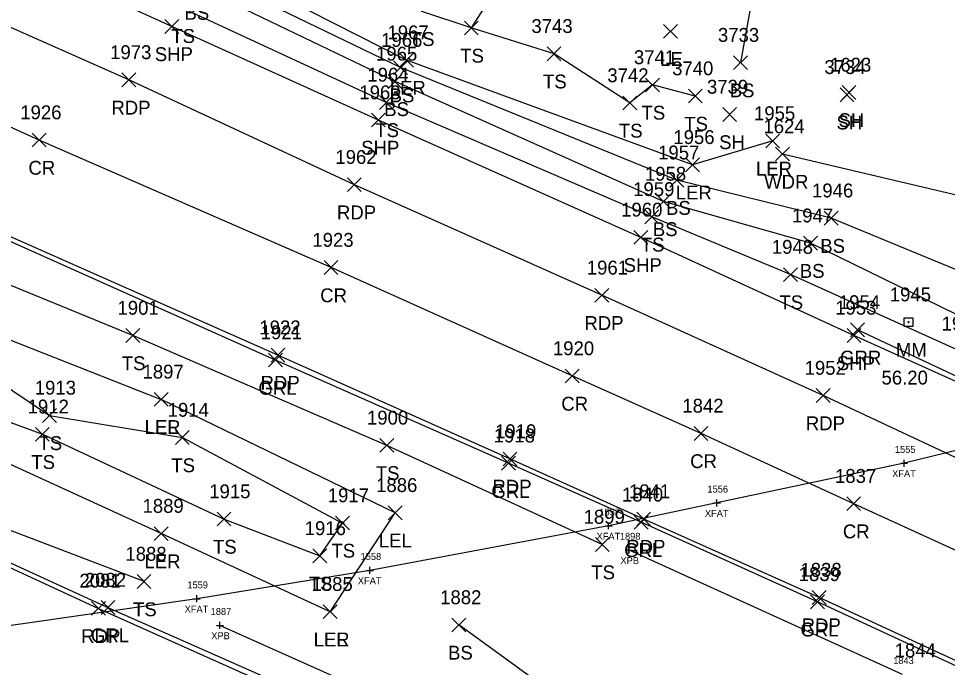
# Model space of a CAD drawing. Extents: x 1599569 to 1610055, y 642560 to 647860.
# Drawn here: x 1601517.7 to 1601651.7, y 647279.1 to 647372.7 of the extents above; entities that cross this region are included whole.
import ezdxf

# ---------------------------------------------------------------- set-up
doc = ezdxf.new("R2010")
doc.units = 0
for name, color, linetype in [('B_A', 7, 'Continuous'), ('B_I', 7, 'Continuous'), ('B_TIC', 7, 'Continuous'), ('BF', 7, 'Continuous'), ('BSUBM', 7, 'Continuous'), ('L_A', 7, 'Continuous'), ('L_I', 7, 'Continuous'), ('L_TIC', 7, 'Continuous'), ('LARO', 7, 'Continuous'), ('LAWA', 7, 'Continuous'), ('LELB', 7, 'Continuous'), ('P_A', 7, 'Continuous'), ('P_I', 7, 'Continuous'), ('P_TIC', 7, 'Continuous'), ('PET', 7, 'Continuous'), ('PRC', 7, 'Continuous'), ('PSP', 7, 'Continuous'), ('R_A', 7, 'Continuous'), ('R_I', 7, 'Continuous'), ('R_TIC', 7, 'Continuous'), ('RGR', 7, 'Continuous'), ('S_A', 7, 'Continuous'), ('S_C', 7, 'Continuous'), ('S_I', 7, 'Continuous'), ('SRM', 7, 'Continuous')]:
    doc.layers.add(name, color=color, linetype=linetype)

msp = doc.modelspace()

# ---------------------------------------------------------------- linework, layer by layer
at = {"layer": 'B_TIC'}
for p, q in [((1601645.46, 647308.52), (1601645.53, 647308.52)), ((1601618.44, 647302.79), (1601618.51, 647302.79)), ((1601602.81, 647299.49), (1601602.88, 647299.49)), ((1601605.77, 647295.98), (1601605.84, 647295.98)), ((1601568.36, 647293.07), (1601568.43, 647293.07)), ((1601543.36, 647288.97), (1601543.44, 647288.97)), ((1601546.72, 647285.13), (1601546.8, 647285.13))]:
    msp.add_line(p, q, dxfattribs=at)
for points in [[(1601645.45, 647308.02), (1601645.45, 647309.02)], [(1601644.95, 647308.52), (1601645.95, 647308.52)], [(1601618.43, 647302.29), (1601618.43, 647303.29)], [(1601617.93, 647302.79), (1601618.93, 647302.79)], [(1601602.3, 647299.49), (1601603.3, 647299.49)], [(1601602.8, 647298.99), (1601602.8, 647299.99)], [(1601605.26, 647295.98), (1601606.26, 647295.98)], [(1601605.76, 647295.48), (1601605.76, 647296.48)], [(1601567.85, 647293.07), (1601568.85, 647293.07)], [(1601568.35, 647292.57), (1601568.35, 647293.57)], [(1601542.86, 647288.97), (1601543.86, 647288.97)], [(1601543.36, 647288.47), (1601543.36, 647289.47)], [(1601546.22, 647285.13), (1601547.22, 647285.13)], [(1601546.72, 647284.63), (1601546.72, 647285.63)]]:
    msp.add_lwpolyline(points, dxfattribs=at)
at = {"layer": 'BF'}
msp.add_lwpolyline([(1601746.01, 647335.35), (1601717.79, 647327.14), (1601692.8, 647320.35), (1601677.17, 647316.27), (1601645.45, 647308.52), (1601618.43, 647302.79), (1601602.8, 647299.49), (1601568.35, 647293.07), (1601543.36, 647288.97), (1601510.51, 647284.26), (1601475.95, 647280.39), (1601455.15, 647278.22), (1601422.22, 647275.79), (1601394.01, 647274.26), (1601380.77, 647273.7), (1601345.12, 647272.82), (1601321.94, 647272.73), (1601290.34, 647273.17)], dxfattribs=at)
at = {"layer": 'BSUBM'}
for points in [[(1601645.21, 647278.05), (1601605.76, 647295.98)], [(1601588.89, 647266.27), (1601546.72, 647285.13)]]:
    msp.add_lwpolyline(points, dxfattribs=at)
at = {"layer": 'L_TIC'}
for points in [[(1601581.98, 647370.32), (1601583.98, 647372.32)], [(1601583.98, 647370.32), (1601581.98, 647372.32)], [(1601581.98, 647370.32), (1601583.98, 647372.32)], [(1601583.98, 647370.32), (1601581.98, 647372.32)], [(1601610.73, 647369.84), (1601612.73, 647371.84)], [(1601612.73, 647369.84), (1601610.73, 647371.84)], [(1601572.63, 647365.69), (1601574.63, 647367.69)], [(1601574.63, 647365.69), (1601572.63, 647367.69)], [(1601593.92, 647366.6), (1601595.92, 647368.6)], [(1601595.92, 647366.6), (1601593.92, 647368.6)], [(1601571.76, 647364.6), (1601573.76, 647366.6)], [(1601573.76, 647364.6), (1601571.76, 647366.6)], [(1601620.83, 647365.32), (1601622.83, 647367.32)], [(1601622.83, 647365.32), (1601620.83, 647367.32)], [(1601570.98, 647362.61), (1601572.98, 647364.61)], [(1601572.98, 647362.61), (1601570.98, 647364.61)], [(1601608.14, 647362.1), (1601610.14, 647364.1)], [(1601610.14, 647362.1), (1601608.14, 647364.1)], [(1601614.31, 647360.5), (1601616.31, 647362.5)], [(1601616.31, 647360.5), (1601614.31, 647362.5)], [(1601636.2, 647360.68), (1601638.2, 647362.68)], [(1601638.2, 647360.68), (1601636.2, 647362.68)], [(1601636.49, 647361.02), (1601638.49, 647363.02)], [(1601638.49, 647361.02), (1601636.49, 647363.02)], [(1601569.72, 647359.58), (1601571.72, 647361.58)], [(1601571.72, 647359.58), (1601569.72, 647361.58)], [(1601604.87, 647359.5), (1601606.87, 647361.5)], [(1601606.87, 647359.5), (1601604.87, 647361.5)], [(1601619.26, 647357.84), (1601621.26, 647359.84)], [(1601621.26, 647357.84), (1601619.26, 647359.84)], [(1601625.48, 647354.02), (1601627.48, 647356.02)], [(1601627.48, 647354.02), (1601625.48, 647356.02)], [(1601626.88, 647352.13), (1601628.88, 647354.13)], [(1601628.88, 647352.13), (1601626.88, 647354.13)], [(1601613.89, 647350.58), (1601615.89, 647352.58)], [(1601615.89, 647350.58), (1601613.89, 647352.58)], [(1601611.64, 647348.36), (1601613.64, 647350.36)], [(1601613.64, 647348.36), (1601611.64, 647350.36)], [(1601609.73, 647345.29), (1601611.73, 647347.29)], [(1601611.73, 647345.29), (1601609.73, 647347.29)], [(1601608.04, 647343.07), (1601610.04, 647345.07)], [(1601610.04, 647343.07), (1601608.04, 647345.07)], [(1601633.9, 647342.88), (1601635.9, 647344.88)], [(1601635.9, 647342.88), (1601633.9, 647344.88)], [(1601630.94, 647339.27), (1601632.94, 647341.27)], [(1601632.94, 647339.27), (1601630.94, 647341.27)], [(1601628.05, 647334.74), (1601630.05, 647336.74)], [(1601630.05, 647334.74), (1601628.05, 647336.74)], [(1601533.14, 647325.95), (1601535.14, 647327.95)], [(1601535.14, 647325.95), (1601533.14, 647327.95)], [(1601537.23, 647316.74), (1601539.23, 647318.74)], [(1601539.23, 647316.74), (1601537.23, 647318.74)], [(1601537.23, 647316.74), (1601539.23, 647318.74)], [(1601539.23, 647316.74), (1601537.23, 647318.74)], [(1601521.12, 647314.42), (1601523.12, 647316.42)], [(1601523.12, 647314.42), (1601521.12, 647316.42)], [(1601520.09, 647311.7), (1601522.09, 647313.7)], [(1601522.09, 647311.7), (1601520.09, 647313.7)], [(1601540.29, 647311.23), (1601542.29, 647313.23)], [(1601542.29, 647311.23), (1601540.29, 647313.23)], [(1601569.79, 647310.1), (1601571.79, 647312.1)], [(1601571.79, 647310.1), (1601569.79, 647312.1)], [(1601571, 647300.37), (1601573, 647302.37)], [(1601573, 647300.37), (1601571, 647302.37)], [(1601546.3, 647299.47), (1601548.3, 647301.47)], [(1601548.3, 647299.47), (1601546.3, 647301.47)], [(1601563.39, 647298.9), (1601565.39, 647300.9)], [(1601565.39, 647298.9), (1601563.39, 647300.9)], [(1601563.39, 647298.9), (1601565.39, 647300.9)], [(1601565.39, 647298.9), (1601563.39, 647300.9)], [(1601537.24, 647297.37), (1601539.24, 647299.37)], [(1601539.24, 647297.37), (1601537.24, 647299.37)], [(1601600.89, 647295.79), (1601602.89, 647297.79)], [(1601602.89, 647295.79), (1601600.89, 647297.79)], [(1601560.12, 647294.15), (1601562.12, 647296.15)], [(1601562.12, 647294.15), (1601560.12, 647296.15)], [(1601534.76, 647290.45), (1601536.76, 647292.45)], [(1601536.76, 647290.45), (1601534.76, 647292.45)], [(1601561.62, 647286.1), (1601563.62, 647288.1)], [(1601563.62, 647286.1), (1601561.62, 647288.1)], [(1601561.62, 647286.1), (1601563.62, 647288.1)], [(1601563.62, 647286.1), (1601561.62, 647288.1)], [(1601580.18, 647284.19), (1601582.18, 647286.19)], [(1601582.18, 647284.19), (1601580.18, 647286.19)]]:
    msp.add_lwpolyline(points, dxfattribs=at)
at = {"layer": 'LARO'}
for points in [[(1601626.48, 647355.02), (1601614.89, 647351.58), (1601573.63, 647366.69), (1601545.56, 647380.95), (1601537.28, 647395.48)], [(1601562.62, 647287.1), (1601538.24, 647298.37), (1601510.12, 647311.25), (1601479.02, 647323.89), (1601477.41, 647331.44), (1601485.68, 647335.15), (1601504.04, 647331.18), (1601538.23, 647317.74)], [(1601562.62, 647287.1), (1601572, 647301.37), (1601538.23, 647317.74)]]:
    msp.add_lwpolyline(points, dxfattribs=at)
at = {"layer": 'LAWA'}
msp.add_lwpolyline([(1601848.49, 647386.96), (1601821.55, 647376.37), (1601804, 647372.6), (1601777.94, 647362.34), (1601760.01, 647349.17), (1601740.19, 647347.52), (1601705.98, 647345.02), (1601664.4, 647344.49), (1601627.88, 647353.13)], dxfattribs=at)
at = {"layer": 'LELB'}
for points in [[(1601623.48, 647409.22), (1601596.3, 647389.79), (1601588.83, 647380.5), (1601582.98, 647371.32), (1601575.85, 647373.72), (1601573.22, 647381.22), (1601572.13, 647391.97), (1601563.55, 647393.07), (1601555.46, 647392.28), (1601552.13, 647388), (1601566.58, 647377.81)], [(1601623.48, 647409.22), (1601626.37, 647391.44), (1601621.83, 647366.32)], [(1601850.43, 647302.21), (1601817.07, 647284.74), (1601803.58, 647280.33), (1601784.13, 647281.69), (1601758.75, 647290.86), (1601723.07, 647307), (1601685.47, 647323.96), (1601675.62, 647324.78), (1601658.01, 647334.35), (1601634.9, 647343.88), (1601612.64, 647349.36), (1601572.76, 647365.6), (1601544.62, 647379.24), (1601520.15, 647401.41)], [(1601803.11, 647261.21), (1601778.68, 647271.51), (1601755.32, 647284.83), (1601720.1, 647301.53), (1601682.66, 647319.41), (1601674.11, 647321.15), (1601654.95, 647329.02), (1601631.94, 647340.27), (1601610.73, 647346.29), (1601571.98, 647363.61), (1601543.15, 647377.5), (1601514.76, 647392.23)], [(1601677.57, 647312.89), (1601653.54, 647324.67), (1601629.05, 647335.74), (1601609.04, 647344.07), (1601570.72, 647360.58), (1601541.29, 647374.16), (1601512.39, 647387.81)], [(1601615.31, 647361.5), (1601609.14, 647363.1), (1601605.87, 647360.5), (1601594.92, 647367.6), (1601582.98, 647371.32)], [(1601601.89, 647296.79), (1601570.79, 647311.1), (1601534.14, 647326.95), (1601503.04, 647339.71), (1601477.7, 647352.04), (1601450.37, 647365.08)], [(1601535.76, 647291.45), (1601504.48, 647303.39), (1601475.12, 647316.86), (1601435.65, 647334.74), (1601403.81, 647348.42)], [(1601485.77, 647329.42), (1601503.55, 647327.86), (1601522.12, 647315.42), (1601541.29, 647312.23), (1601564.39, 647299.9)], [(1601485.77, 647329.42), (1601503.31, 647319.28), (1601521.09, 647312.7), (1601547.3, 647300.47), (1601561.12, 647295.15), (1601564.39, 647299.9)], [(1601962.97, 647113.31), (1601923.69, 647130.08), (1601895.55, 647143.8), (1601852.73, 647162.89), (1601817.77, 647178.58), (1601769.5, 647198.02), (1601730.98, 647216.5), (1601688.1, 647233.1), (1601653.57, 647246.64), (1601608.27, 647265.53), (1601581.18, 647285.19)]]:
    msp.add_lwpolyline(points, dxfattribs=at)
at = {"layer": 'P_TIC'}
for points in [[(1601538.77, 647370.54), (1601540.77, 647372.54)], [(1601540.77, 647370.54), (1601538.77, 647372.54)], [(1601532.57, 647362.83), (1601534.57, 647364.83)], [(1601534.57, 647362.83), (1601532.57, 647364.83)], [(1601568.57, 647357.04), (1601570.57, 647359.04)], [(1601570.57, 647357.04), (1601568.57, 647359.04)], [(1601519.64, 647354.15), (1601521.64, 647356.15)], [(1601521.64, 647354.15), (1601519.64, 647356.15)], [(1601565.11, 647347.71), (1601567.11, 647349.71)], [(1601567.11, 647347.71), (1601565.11, 647349.71)], [(1601606.44, 647340.11), (1601608.44, 647342.11)], [(1601608.44, 647340.11), (1601606.44, 647342.11)], [(1601561.74, 647335.75), (1601563.74, 647337.75)], [(1601563.74, 647335.75), (1601561.74, 647337.75)], [(1601600.82, 647331.75), (1601602.82, 647333.75)], [(1601602.82, 647331.75), (1601600.82, 647333.75)], [(1601637.2, 647325.96), (1601639.2, 647327.96)], [(1601639.2, 647325.96), (1601637.2, 647327.96)], [(1601554.09, 647323.12), (1601556.09, 647325.12)], [(1601556.09, 647323.12), (1601554.09, 647325.12)], [(1601596.54, 647320.11), (1601598.54, 647322.11)], [(1601598.54, 647320.11), (1601596.54, 647322.11)], [(1601632.77, 647317.29), (1601634.77, 647319.29)], [(1601634.77, 647317.29), (1601632.77, 647319.29)], [(1601615.13, 647311.82), (1601617.13, 647313.82)], [(1601617.13, 647311.82), (1601615.13, 647313.82)], [(1601587.56, 647308.14), (1601589.56, 647310.14)], [(1601589.56, 647308.14), (1601587.56, 647310.14)], [(1601637.16, 647301.69), (1601639.16, 647303.69)], [(1601639.16, 647301.69), (1601637.16, 647303.69)], [(1601606.86, 647299.47), (1601608.86, 647301.47)], [(1601608.86, 647299.47), (1601606.86, 647301.47)], [(1601632.17, 647288.14), (1601634.17, 647290.14)], [(1601634.17, 647288.14), (1601632.17, 647290.14)], [(1601528.2, 647286.58), (1601530.2, 647288.58)], [(1601530.2, 647286.58), (1601528.2, 647288.58)]]:
    msp.add_lwpolyline(points, dxfattribs=at)
at = {"layer": 'PET'}
for points in [[(1602047.79, 647130.94), (1602008.9, 647148.2), (1601944.5, 647177.36), (1601896.5, 647199.08), (1601839.98, 647224.8), (1601799.6, 647242.94), (1601761.01, 647260.23), (1601722.86, 647277.56), (1601690.61, 647292.09), (1601662.07, 647305.04), (1601633.77, 647318.29), (1601601.82, 647332.75), (1601566.11, 647348.71), (1601533.57, 647363.83), (1601469.6, 647392.2)], [(1601973.38, 647134.15), (1601930.79, 647153.54), (1601888.64, 647172.44), (1601843.17, 647192.94), (1601801.06, 647212.25), (1601760.52, 647230.65), (1601718.64, 647249.66), (1601675.39, 647269.62), (1601633.17, 647289.14), (1601607.86, 647300.47), (1601588.56, 647309.14), (1601555.09, 647324.12), (1601512, 647343.16), (1601472.14, 647361.1), (1601457.8, 647367.35)], [(1601401.84, 647345.99), (1601436.76, 647329.85), (1601477.89, 647310.69), (1601511.69, 647295.64), (1601529.2, 647287.58), (1601568.21, 647270.13), (1601613.57, 647249.46), (1601666.31, 647226.36), (1601709.07, 647207.41), (1601751.08, 647188.42), (1601796.47, 647168.32), (1601839.63, 647148.76), (1601881.89, 647129.58), (1601912.89, 647115.63)]]:
    msp.add_lwpolyline(points, dxfattribs=at)
at = {"layer": 'PRC'}
msp.add_lwpolyline([(1602004.91, 647136.4), (1601979.09, 647147.72), (1601938.18, 647166.06), (1601894.66, 647185.48), (1601851.67, 647205.52), (1601807.6, 647224.86), (1601766.29, 647241.91), (1601725.38, 647262.23), (1601683.79, 647281.85), (1601638.16, 647302.69), (1601616.13, 647312.82), (1601597.54, 647321.11), (1601562.74, 647336.75), (1601520.64, 647355.15), (1601479.31, 647373.89)], dxfattribs=at)
at = {"layer": 'PSP'}
msp.add_lwpolyline([(1602119.04, 647109.91), (1602086.42, 647124.41), (1602045.38, 647142.93), (1602000.82, 647163.15), (1601951.88, 647184.91), (1601900.46, 647208.01), (1601848.64, 647231.74), (1601816.21, 647246.31), (1601775.91, 647264.22), (1601751.81, 647275.4), (1601715.81, 647291.56), (1601673.9, 647310.83), (1601638.2, 647326.96), (1601607.44, 647341.11), (1601569.57, 647358.04), (1601539.77, 647371.54), (1601489.48, 647394.4)], dxfattribs=at)
at = {"layer": 'R_TIC'}
for points in [[(1601637.71, 647326.76), (1601639.71, 647328.76)], [(1601639.71, 647326.76), (1601637.71, 647328.76)], [(1601553.72, 647322.41), (1601555.72, 647324.41)], [(1601555.72, 647322.41), (1601553.72, 647324.41)], [(1601587.34, 647307.52), (1601589.34, 647309.52)], [(1601589.34, 647307.52), (1601587.34, 647309.52)], [(1601606.5, 647299), (1601608.5, 647301)], [(1601608.5, 647299), (1601606.5, 647301)], [(1601529.55, 647286.7), (1601531.55, 647288.7)], [(1601531.55, 647286.7), (1601529.55, 647288.7)], [(1601631.93, 647287.53), (1601633.93, 647289.53)], [(1601633.93, 647287.53), (1601631.93, 647289.53)]]:
    msp.add_lwpolyline(points, dxfattribs=at)
at = {"layer": 'RGR'}
for points in [[(1601973.06, 647133.72), (1601930.49, 647152.82), (1601887.99, 647171.84), (1601842.93, 647192.4), (1601800.73, 647211.54), (1601759.97, 647229.98), (1601718.53, 647248.97), (1601675.12, 647269.02), (1601632.93, 647288.53), (1601607.5, 647300), (1601588.34, 647308.52), (1601554.72, 647323.41), (1601511.66, 647342.62), (1601471.88, 647360.48), (1601457.01, 647367.11)], [(1601402.77, 647346.31), (1601437.17, 647330.45), (1601512.1, 647296.13), (1601530.55, 647287.7), (1601568.72, 647270.81), (1601614.15, 647250.08), (1601638.3, 647239.5)], [(1602119.22, 647110.24), (1602086.6, 647124.69), (1602045.91, 647143.17), (1602000.94, 647163.41), (1601952.66, 647185.37), (1601901.1, 647208.39), (1601848.7, 647232.28), (1601817.54, 647246.54), (1601776.21, 647264.77), (1601751.92, 647275.79), (1601716.14, 647291.92), (1601674.23, 647311.09), (1601638.71, 647327.76)]]:
    msp.add_lwpolyline(points, dxfattribs=at)
at = {"layer": 'SRM'}
msp.add_lwpolyline([(1601645.44, 647329.51), (1601646.69, 647329.51), (1601646.69, 647328.26), (1601645.44, 647328.26)], close=True, dxfattribs=at)
msp.add_circle((1601646.06, 647328.88), 0.0833, dxfattribs=at)

# ---------------------------------------------------------------- texts
at = {"layer": 'B_A'}
for s, p in [('XFAT', (1601643.71, 647306.52)), ('XFAT', (1601616.69, 647300.79)), ('XFAT', (1601601.06, 647297.49)), ('XPB', (1601604.5, 647293.98)), ('XFAT', (1601566.61, 647291.07)), ('XFAT', (1601541.62, 647286.97)), ('XPB', (1601545.46, 647283.13))]:
    msp.add_text(s, height=1, dxfattribs=at).set_placement(p)
at = {"layer": 'B_I'}
for s, p in [('1555', (1601644.11, 647310.02)), ('1556', (1601617.06, 647304.29)), ('1557', (1601601.46, 647300.99)), ('1898', (1601604.42, 647297.48)), ('1558', (1601567.01, 647294.57)), ('1559', (1601542.01, 647290.47)), ('1887', (1601545.37, 647286.63)), ('1843', (1601643.86, 647279.55))]:
    msp.add_text(s, height=1, dxfattribs=at).set_placement(p)
at = {"layer": 'L_A'}
for s, p in [('BS', (1601541.59, 647372.5)), ('TS', (1601539.7, 647369.16)), ('TS', (1601574.26, 647368.72)), ('TS', (1601581.39, 647366.32)), ('TS', (1601581.39, 647366.32)), ('LE', (1601610.22, 647365.84)), ('LER', (1601571.21, 647361.69)), ('TS', (1601593.33, 647362.6)), ('BS', (1601571.2, 647360.6)), ('BS', (1601620.27, 647361.32)), ('BS', (1601570.42, 647358.61)), ('TS', (1601607.55, 647358.1)), ('TS', (1601613.72, 647356.5)), ('SH', (1601635.68, 647356.68)), ('SH', (1601635.98, 647357.02)), ('TS', (1601569.13, 647355.58)), ('TS', (1601604.28, 647355.5)), ('SH', (1601618.75, 647353.84)), ('LER', (1601624.06, 647350.02)), ('WDR', (1601625.24, 647348.13)), ('LER', (1601612.48, 647346.58)), ('BS', (1601611.08, 647344.36)), ('BS', (1601609.18, 647341.29)), ('TS', (1601607.45, 647339.07)), ('BS', (1601633.34, 647338.88)), ('BS', (1601630.39, 647335.27)), ('TS', (1601627.45, 647330.74)), ('TS', (1601532.55, 647321.95)), ('LER', (1601535.82, 647312.74)), ('LEL', (1601535.87, 647312.74)), ('TS', (1601520.53, 647310.42)), ('TS', (1601519.5, 647307.7)), ('TS', (1601539.7, 647307.23)), ('TS', (1601569.2, 647306.1)), ('LEL', (1601569.64, 647296.37)), ('TS', (1601545.71, 647295.47)), ('TS', (1601562.8, 647294.9)), ('TS', (1601562.8, 647294.9)), ('LER', (1601535.82, 647293.37)), ('TS', (1601600.3, 647291.79)), ('TS', (1601559.53, 647290.15)), ('TS', (1601534.17, 647286.45)), ('LER', (1601560.21, 647282.1)), ('LEL', (1601560.26, 647282.1)), ('BS', (1601579.63, 647280.19))]:
    msp.add_text(s, height=2, dxfattribs=at).set_placement(p)
at = {"layer": 'L_I'}
for s, p in [('1967', (1601570.89, 647369.69)), ('3743', (1601591.66, 647370.6)), ('1966', (1601569.97, 647368.6)), ('3733', (1601618.57, 647369.32)), ('1965', (1601569.24, 647366.61)), ('3741', (1601606.44, 647366.1)), ('3740', (1601611.96, 647364.5)), ('3734', (1601633.94, 647364.68)), ('1623', (1601634.75, 647365.02)), ('1964', (1601567.98, 647363.58)), ('3742', (1601602.61, 647363.5)), ('3739', (1601616.99, 647361.84)), ('1955', (1601623.78, 647358.02)), ('1624', (1601625.14, 647356.13)), ('1956', (1601612.14, 647354.58)), ('1957', (1601609.94, 647352.36)), ('1958', (1601608.04, 647349.29)), ('1959', (1601606.34, 647347.07)), ('1946', (1601632.15, 647346.88)), ('1947', (1601629.25, 647343.27)), ('1948', (1601626.35, 647338.74)), ('1901', (1601531.93, 647329.95)), ('1942', (1601650.85, 647327.67)), ('1897', (1601535.54, 647320.74)), ('1897', (1601535.54, 647320.74)), ('1913', (1601519.99, 647318.42)), ('1912', (1601518.96, 647315.7)), ('1914', (1601539.17, 647315.23)), ('1900', (1601567.93, 647314.1)), ('1886', (1601569.25, 647304.37)), ('1915', (1601545.17, 647303.47)), ('1917', (1601562.27, 647302.9)), ('1917', (1601562.27, 647302.9)), ('1889', (1601535.54, 647301.37)), ('1899', (1601599.19, 647299.79)), ('1916', (1601558.94, 647298.15)), ('1888', (1601533.07, 647294.45)), ('1885', (1601559.93, 647290.1)), ('1885', (1601559.93, 647290.1)), ('1882', (1601578.49, 647288.19)), ('1844', (1601644.08, 647280.53))]:
    msp.add_text(s, height=2, dxfattribs=at).set_placement(p)
at = {"layer": 'P_A'}
for s, p in [('SHP', (1601537.31, 647366.54)), ('RDP', (1601531.05, 647358.83)), ('SHP', (1601567.1, 647353.04)), ('CR', (1601519.08, 647350.15)), ('RDP', (1601563.6, 647343.71)), ('SHP', (1601604.97, 647336.11)), ('CR', (1601561.18, 647331.75)), ('RDP', (1601599.31, 647327.75)), ('SHP', (1601635.73, 647321.96)), ('RDP', (1601552.58, 647319.12)), ('CR', (1601595.97, 647316.11)), ('RDP', (1601631.26, 647313.29)), ('CR', (1601614.57, 647307.82)), ('RDP', (1601586.04, 647304.14)), ('CR', (1601636.6, 647297.69)), ('RDP', (1601605.35, 647295.47)), ('RDP', (1601630.66, 647284.14)), ('RDP', (1601526.69, 647282.58))]:
    msp.add_text(s, height=2, dxfattribs=at).set_placement(p)
at = {"layer": 'P_I'}
for s, p in [('1973', (1601530.87, 647366.83)), ('1963', (1601566.83, 647361.04)), ('1926', (1601517.9, 647358.15)), ('1962', (1601563.37, 647351.71)), ('1960', (1601604.61, 647344.11)), ('1923', (1601560.05, 647339.75)), ('1961', (1601599.65, 647335.75)), ('1953', (1601635.5, 647329.96)), ('1922', (1601552.4, 647327.12)), ('1920', (1601594.76, 647324.11)), ('1952', (1601631.08, 647321.29)), ('1842', (1601613.44, 647315.82)), ('1919', (1601586.42, 647312.14)), ('1837', (1601635.47, 647305.69)), ('1841', (1601605.73, 647303.47)), ('1838', (1601630.48, 647292.14)), ('2081', (1601526.43, 647290.58))]:
    msp.add_text(s, height=2, dxfattribs=at).set_placement(p)
at = {"layer": 'R_A'}
for s, p in [('GRR', (1601636.2, 647322.76)), ('GRL', (1601552.27, 647318.41)), ('GRL', (1601585.89, 647303.52)), ('GRL', (1601605.04, 647295)), ('GRL', (1601528.09, 647282.7)), ('GRL', (1601630.48, 647283.53))]:
    msp.add_text(s, height=2, dxfattribs=at).set_placement(p)
at = {"layer": 'R_I'}
for s, p in [('1954', (1601636.02, 647330.76)), ('1921', (1601552.6, 647326.41)), ('1918', (1601586.22, 647311.52)), ('1840', (1601604.72, 647303)), ('2082', (1601527.21, 647290.7)), ('1839', (1601630.23, 647291.53))]:
    msp.add_text(s, height=2, dxfattribs=at).set_placement(p)
at = {"layer": 'S_A'}
msp.add_text('MM', height=2, dxfattribs=at).set_placement((1601644.25, 647323.88))
at = {"layer": 'S_C'}
msp.add_text('56.20', height=2, dxfattribs=at).set_placement((1601642.18, 647319.88))
at = {"layer": 'S_I'}
msp.add_text('1945', height=2, dxfattribs=at).set_placement((1601643.37, 647331.88))

doc.saveas('drawing.dxf')
